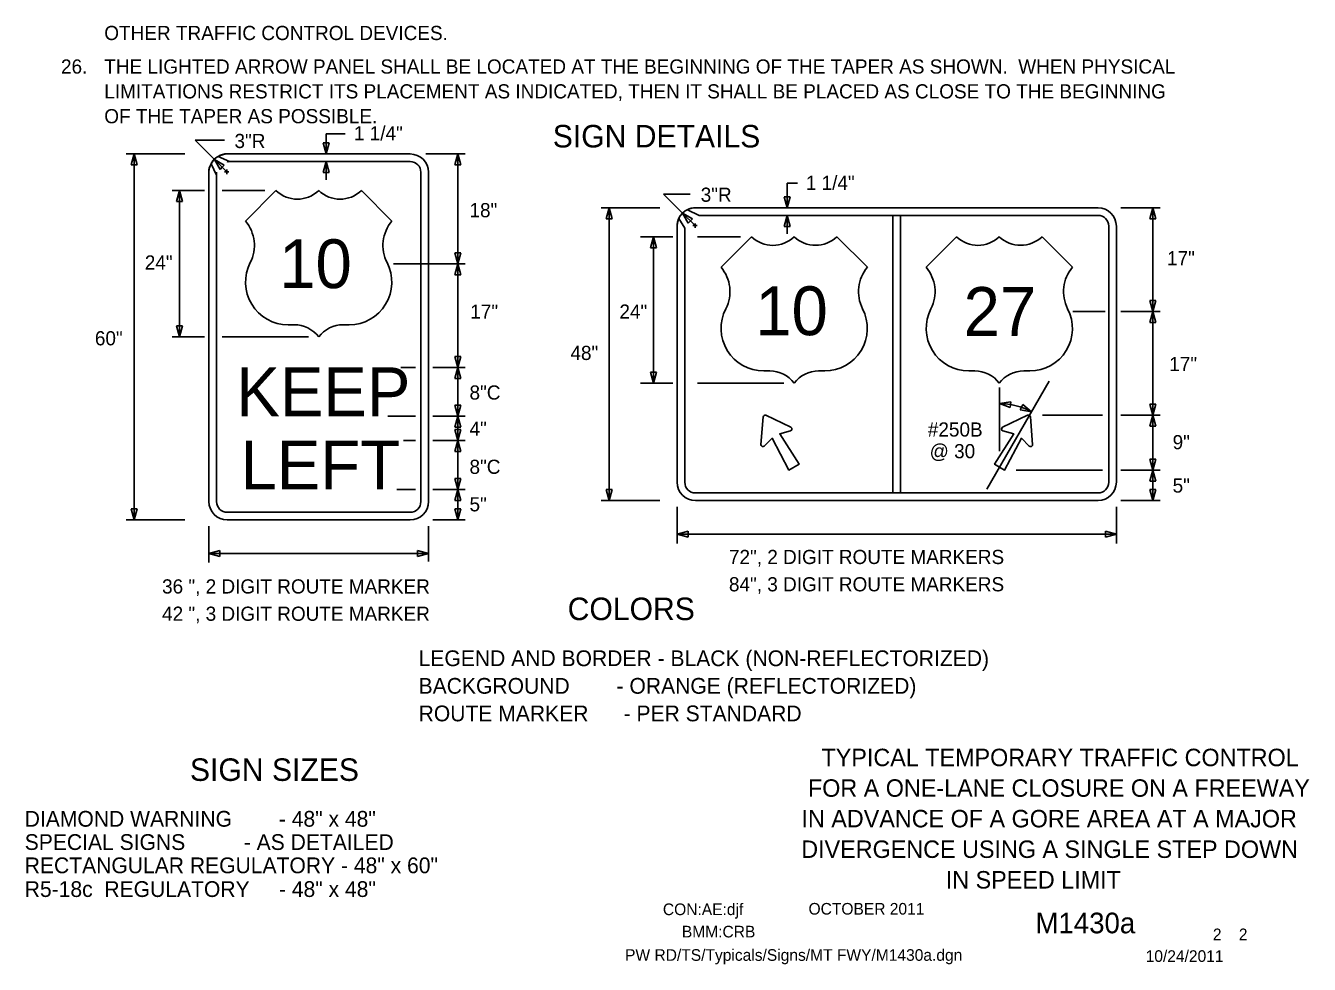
# Model space of a CAD drawing. Extents: x 16729 to 18500, y 5737 to 6974.
# Drawn here: x 17780 to 18464, y 5932 to 6432 of the extents above; entities that cross this region are included whole.
import ezdxf

# ---------------------------------------------------------------- set-up
doc = ezdxf.new("R2010")
doc.units = 0
for name, color, linetype in [('BORDER', 7, 'Continuous'), ('BORDER_SIGNAL_WO', 7, 'Continuous'), ('TRAFFIC_SIGNS_PR', 7, 'Continuous'), ('TYPICAL_EX', 7, 'Continuous'), ('TYPICAL_TEXT_DIMEN_PR', 7, 'Continuous')]:
    doc.layers.add(name, color=color, linetype=linetype)

msp = doc.modelspace()

# ---------------------------------------------------------------- linework, layer by layer
at = {"layer": 'TRAFFIC_SIGNS_PR'}
for p, q in [((17888.74, 6359.64), (17882.64, 6362.38)), ((17887.54, 6363.7), (17985.04, 6363.7)), ((17879.95, 6360.08), (17878.95, 6358.57)), ((17878.98, 6358.5), (17881.85, 6352.46)), ((17985.04, 6359.64), (17887.54, 6359.64)), ((17877.79, 6178.45), (17877.79, 6353.95)), ((17881.85, 6353.95), (17881.85, 6178.45)), ((17990.72, 6178.45), (17990.72, 6353.95)), ((17994.79, 6353.95), (17994.79, 6178.45)), ((18139.01, 6330.95), (18132.78, 6333.97)), ((18137.06, 6335), (18351.56, 6335)), ((18137.06, 6335), (18351.56, 6335)), ((18128.23, 6329.26), (18131.37, 6324.21)), ((18138.99, 6330.94), (18242.28, 6330.94)), ((18351.56, 6330.94), (18139, 6330.94)), ((18242.28, 6330.94), (18242.28, 6183.06)), ((18246.34, 6330.94), (18246.34, 6183.06)), ((18246.34, 6330.94), (18351.56, 6330.94)), ((18127.31, 6325.25), (18127.31, 6188.75)), ((18127.31, 6188.75), (18127.31, 6325.25)), ((18131.37, 6324.2), (18131.37, 6188.75)), ((18131.37, 6324.2), (18131.37, 6188.75)), ((18357.24, 6325.25), (18357.24, 6279.5)), ((18357.25, 6188.75), (18357.25, 6325.25)), ((18361.31, 6325.25), (18361.31, 6188.75)), ((18361.31, 6325.25), (18361.31, 6188.75)), ((18357.24, 6279.5), (18357.24, 6188.75)), ((18174.57, 6224.44), (18187.89, 6218.08)), ((18314.04, 6224.44), (18300.73, 6218.08)), ((18171.91, 6208.86), (18173.06, 6223.57)), ((18316.71, 6208.86), (18315.56, 6223.57)), ((18137.06, 6183.06), (18351.56, 6183.06)), ((18137.06, 6179), (18351.56, 6179)), ((18351.56, 6179), (18137.06, 6179)), ((17887.54, 6172.76), (17985.04, 6172.76)), ((17985.04, 6168.7), (17887.54, 6168.7))]:
    msp.add_line(p, q, dxfattribs=at)
for points in [[(18139, 6330.94), (18138.98, 6330.94)], [(18131.37, 6324.21), (18131.37, 6324.2)], [(18187.73, 6216.11), (18182, 6214.54), (18192.22, 6198.37), (18186.82, 6195.25), (18177.93, 6212.19), (18173.7, 6208.02)], [(18300.89, 6216.11), (18306.61, 6214.54), (18296.4, 6198.37), (18301.79, 6195.25), (18310.69, 6212.19), (18314.91, 6208.02)]]:
    msp.add_lwpolyline(points, dxfattribs=at)
msp.add_lwpolyline([(18242.28, 6330.94), (18246.34, 6330.94), (18246.34, 6183.06), (18242.28, 6183.06)], close=True, dxfattribs=at)
for centre, radius, start, end in [((17887.54, 6353.95), 9.75, 90, 180), ((17886.95, 6356.12), 7.6, 85.58319, 124.53531), ((17985.04, 6353.95), 9.75, 0, 90), ((17884.82, 6354.54), 7.06, 145.86811, 184.82317), ((17888.14, 6364.06), 4.47, 262.2432, 277.7568), ((17985.04, 6353.95), 5.69, 0, 90), ((17876.39, 6353.2), 5.51, 352.24294, 7.75653), ((18137.06, 6325.25), 9.75, 90, 180), ((18137.06, 6325.25), 9.75, 90, 180), ((18136.38, 6328.43), 6.6, 84.11162, 123.06374), ((18351.56, 6325.25), 9.75, 0, 90), ((18351.56, 6325.25), 9.75, 0, 90), ((18133.44, 6325.95), 6.17, 147.60925, 186.56283), ((18138, 6338.12), 7.24, 277.81035, 278.05403), ((18351.56, 6325.25), 5.69, 0, 89.99421), ((18351.56, 6325.25), 5.69, 0, 90), ((18174.12, 6223.49), 1.06, 64.48226, 175.51774), ((18314.5, 6223.49), 1.06, 4.48226, 115.51774), ((18187.43, 6217.13), 1.06, 285.9885, 64.48226), ((18301.18, 6217.13), 1.06, 115.51774, 254.0115), ((18172.97, 6208.78), 1.06, 175.51775, 314.01151), ((18315.65, 6208.78), 1.06, 225.98849, 4.48225), ((18137.06, 6188.75), 9.75, 180, 270), ((18137.06, 6188.75), 9.75, 180, 270), ((18137.06, 6188.75), 5.69, 180, 270), ((18137.06, 6188.75), 5.69, 180, 270), ((18351.56, 6188.75), 9.75, 270, 0), ((18351.56, 6188.75), 5.69, 270, 0), ((18351.56, 6188.75), 9.75, 270, 0), ((18351.56, 6188.75), 5.69, 270, 0), ((17887.54, 6178.45), 9.75, 180, 270), ((17887.54, 6178.45), 5.69, 180, 270), ((17985.04, 6178.45), 5.69, 270, 0), ((17985.04, 6178.45), 9.75, 270, 0)]:
    msp.add_arc(centre, radius, start, end, dxfattribs=at)
at = {"layer": 'TYPICAL_EX'}
for p, q in [((17897.29, 6327.95), (17913.54, 6344.2)), ((17975.29, 6327.95), (17959.04, 6344.2)), ((18150.67, 6303.34), (18166.92, 6319.59)), ((18228.67, 6303.34), (18212.42, 6319.59)), ((18259.95, 6303.34), (18276.2, 6319.59)), ((18337.95, 6303.34), (18321.7, 6319.59)), ((17920.01, 6272.66), (17923.26, 6272.66)), ((17952.56, 6272.66), (17949.31, 6272.66)), ((18173.4, 6248.05), (18176.65, 6248.05)), ((18205.94, 6248.05), (18202.69, 6248.05)), ((18282.67, 6248.05), (18285.92, 6248.05)), ((18315.22, 6248.05), (18311.97, 6248.05))]:
    msp.add_line(p, q, dxfattribs=at)
for centre, radius, start, end in [((17924.91, 6356.03), 16.42, 226.14041, 313.85958), ((17947.66, 6356.04), 16.42, 226.14042, 313.85959), ((17881.88, 6314.94), 20.16, 333.09768, 40.19361), ((17990.69, 6314.94), 20.16, 139.80639, 206.90233), ((18178.3, 6331.42), 16.42, 226.14041, 313.85958), ((18201.04, 6331.43), 16.42, 226.14042, 313.85959), ((18287.57, 6331.42), 16.42, 226.14041, 313.85958), ((18310.32, 6331.43), 16.42, 226.14042, 313.85959), ((17920.05, 6295.38), 22.73, 152.6698, 269.90132), ((17952.52, 6295.38), 22.73, 270.09868, 27.3302), ((18135.27, 6290.33), 20.16, 333.09768, 40.19361), ((18244.07, 6290.33), 20.16, 139.80639, 206.90233), ((18244.55, 6290.33), 20.16, 333.09768, 40.19361), ((18353.35, 6290.33), 20.16, 139.80639, 206.90233), ((18173.44, 6270.77), 22.73, 152.6698, 269.90132), ((18205.9, 6270.77), 22.73, 270.09868, 27.3302), ((18282.71, 6270.77), 22.73, 152.6698, 269.90132), ((18315.18, 6270.77), 22.73, 270.09868, 27.3302), ((17923.3, 6256.38), 16.28, 37.1038, 90.13853), ((17949.27, 6256.38), 16.28, 89.86147, 142.8962), ((18176.69, 6231.77), 16.28, 37.1038, 90.13853), ((18202.65, 6231.77), 16.28, 89.86147, 142.8962), ((18285.97, 6231.77), 16.28, 37.1038, 90.13853), ((18311.93, 6231.77), 16.28, 89.86147, 142.8962)]:
    msp.add_arc(centre, radius, start, end, dxfattribs=at)
at = {"layer": 'TYPICAL_TEXT_DIMEN_PR'}
for p, q in [((17886.16, 6370.98), (17870.5, 6370.98)), ((17870.5, 6370.98), (17880.74, 6360.74)), ((17940.26, 6363.7), (17938.69, 6369.56)), ((17938.69, 6369.56), (17940.26, 6369.56)), ((17940.26, 6374.46), (17940.26, 6363.7)), ((17940.26, 6374.46), (17950.36, 6374.46)), ((17940.26, 6369.56), (17941.83, 6369.56)), ((17941.83, 6369.56), (17940.26, 6363.7)), ((17864.96, 6363.7), (17833.66, 6363.7)), ((17836.43, 6357.84), (17838, 6363.7)), ((17838, 6363.7), (17838, 6168.7)), ((17838, 6363.7), (17839.57, 6357.84)), ((17993.33, 6363.7), (18014.29, 6363.7)), ((18008.82, 6357.84), (18010.39, 6363.7)), ((18010.39, 6363.7), (18010.39, 6305.2)), ((18010.39, 6363.7), (18011.96, 6357.84)), ((17838, 6357.84), (17836.43, 6357.84)), ((17839.57, 6357.84), (17838, 6357.84)), ((17880.74, 6360.74), (17887.3, 6354.19)), ((17883.77, 6355.49), (17880.74, 6360.74)), ((17880.74, 6360.74), (17885.99, 6357.71)), ((17884.88, 6356.6), (17883.77, 6355.49)), ((17885.99, 6357.71), (17884.88, 6356.6)), ((17886.09, 6354.19), (17888.5, 6354.19)), ((17887.3, 6352.98), (17887.3, 6355.4)), ((17938.74, 6353.77), (17940.31, 6359.64)), ((17940.31, 6359.64), (17940.31, 6349.89)), ((17940.31, 6359.64), (17941.88, 6353.77)), ((18010.39, 6357.84), (18008.82, 6357.84)), ((18011.96, 6357.84), (18010.39, 6357.84)), ((17940.31, 6353.77), (17938.74, 6353.77)), ((17941.88, 6353.77), (17940.31, 6353.77)), ((18185.92, 6348.15), (18185.92, 6335)), ((18185.92, 6348.15), (18191.44, 6348.15)), ((17875.41, 6344.2), (17858.29, 6344.2)), ((17860.61, 6338.34), (17862.18, 6344.2)), ((17862.18, 6344.2), (17862.18, 6266.2)), ((17862.18, 6344.2), (17863.75, 6338.34)), ((17907.65, 6344.2), (17884.78, 6344.2)), ((18134.2, 6342.28), (18120.02, 6342.28)), ((18120.02, 6342.28), (18130.17, 6332.14)), ((18185.92, 6335), (18184.34, 6340.86)), ((18184.34, 6340.86), (18185.92, 6340.86)), ((18185.92, 6340.86), (18187.49, 6340.86)), ((18187.49, 6340.86), (18185.92, 6335)), ((17862.18, 6338.34), (17860.61, 6338.34)), ((17863.75, 6338.34), (17862.18, 6338.34)), ((18118.08, 6335), (18086.78, 6335)), ((18089.55, 6329.14), (18091.12, 6335)), ((18091.12, 6335), (18091.12, 6179)), ((18091.12, 6335), (18092.69, 6329.14)), ((18363.68, 6335), (18384.64, 6335)), ((18379.17, 6329.14), (18380.74, 6335)), ((18380.74, 6335), (18380.74, 6279.75)), ((18380.74, 6335), (18382.31, 6329.14)), ((18091.12, 6329.14), (18089.55, 6329.14)), ((18092.69, 6329.14), (18091.12, 6329.14)), ((18130.17, 6332.14), (18136.82, 6325.49)), ((18133.21, 6326.88), (18130.17, 6332.14)), ((18130.17, 6332.14), (18135.43, 6329.1)), ((18134.32, 6327.99), (18133.21, 6326.88)), ((18135.43, 6329.1), (18134.32, 6327.99)), ((18184.39, 6325.07), (18185.96, 6330.94)), ((18184.39, 6325.07), (18185.96, 6330.94)), ((18185.96, 6330.94), (18185.96, 6321.19)), ((18185.96, 6330.94), (18187.53, 6325.07)), ((18185.96, 6330.94), (18187.53, 6325.07)), ((18380.74, 6329.14), (18379.17, 6329.14)), ((18382.31, 6329.14), (18380.74, 6329.14)), ((18135.61, 6325.49), (18138.03, 6325.49)), ((18136.82, 6324.28), (18136.82, 6326.7)), ((18185.96, 6325.07), (18184.39, 6325.07)), ((18185.96, 6325.07), (18184.39, 6325.07)), ((18187.53, 6325.07), (18185.96, 6325.07)), ((18187.53, 6325.07), (18185.96, 6325.07)), ((18124.94, 6319.59), (18107.81, 6319.59)), ((18113.1, 6313.73), (18114.67, 6319.59)), ((18114.67, 6313.73), (18113.1, 6313.73)), ((18114.67, 6319.59), (18114.67, 6241.59)), ((18114.67, 6319.59), (18116.25, 6313.73)), ((18116.25, 6313.73), (18114.67, 6313.73)), ((18161.04, 6319.59), (18138.16, 6319.59)), ((18010.39, 6305.2), (18008.82, 6311.06)), ((18008.82, 6311.06), (18010.39, 6311.06)), ((18010.39, 6311.06), (18011.96, 6311.06)), ((18011.96, 6311.06), (18010.39, 6305.2)), ((17976.18, 6305.2), (18014.29, 6305.2)), ((18008.82, 6299.34), (18010.39, 6305.2)), ((18010.39, 6305.2), (18010.39, 6249.95)), ((18010.39, 6305.2), (18011.96, 6299.34)), ((18010.39, 6299.34), (18008.82, 6299.34)), ((18011.96, 6299.34), (18010.39, 6299.34)), ((18338.12, 6279.75), (18355.27, 6279.75)), ((18363.68, 6279.75), (18384.64, 6279.75)), ((18380.74, 6279.75), (18379.17, 6285.61)), ((18379.17, 6285.61), (18380.74, 6285.61)), ((18379.17, 6273.89), (18380.74, 6279.75)), ((18380.74, 6285.61), (18382.31, 6285.61)), ((18382.31, 6285.61), (18380.74, 6279.75)), ((18380.74, 6279.75), (18380.74, 6224.5)), ((18380.74, 6279.75), (18382.31, 6273.89)), ((18380.74, 6273.89), (18379.17, 6273.89)), ((18382.31, 6273.89), (18380.74, 6273.89)), ((17875.41, 6266.2), (17858.29, 6266.2)), ((17862.18, 6266.2), (17860.61, 6272.06)), ((17860.61, 6272.06), (17862.18, 6272.06)), ((17862.18, 6272.06), (17863.75, 6272.06)), ((17863.75, 6272.06), (17862.18, 6266.2)), ((17930.78, 6266.2), (17884.78, 6266.2)), ((18010.39, 6249.95), (18008.82, 6255.81)), ((18008.82, 6255.81), (18010.39, 6255.81)), ((18010.39, 6255.81), (18011.96, 6255.81)), ((18011.96, 6255.81), (18010.39, 6249.95)), ((17980.11, 6249.95), (17987.8, 6249.95)), ((17997.16, 6249.95), (18014.29, 6249.95)), ((18008.82, 6244.09), (18010.39, 6249.95)), ((18010.39, 6249.95), (18010.39, 6223.95)), ((18010.39, 6249.95), (18011.96, 6244.09)), ((18114.67, 6241.59), (18113.1, 6247.45)), ((18113.1, 6247.45), (18114.67, 6247.45)), ((18114.67, 6247.45), (18116.25, 6247.45)), ((18116.25, 6247.45), (18114.67, 6241.59)), ((18010.39, 6244.09), (18008.82, 6244.09)), ((18011.96, 6244.09), (18010.39, 6244.09)), ((18124.94, 6241.59), (18107.81, 6241.59)), ((18184.16, 6241.59), (18138.16, 6241.59)), ((18292.34, 6185.1), (18325.58, 6242.69)), ((18299.1, 6205.25), (18299.1, 6239.25)), ((18299.12, 6230.69), (18305.12, 6231.65)), ((18305.12, 6231.65), (18304.96, 6230.09)), ((18010.39, 6223.95), (18008.82, 6229.81)), ((18008.82, 6229.81), (18010.39, 6229.81)), ((18010.39, 6229.81), (18011.96, 6229.81)), ((18011.96, 6229.81), (18010.39, 6223.95)), ((18304.8, 6228.53), (18299.12, 6230.69)), ((18304.96, 6230.09), (18304.8, 6228.53)), ((18310.11, 6227.37), (18310.79, 6228.78)), ((18316.08, 6226.24), (18310.11, 6227.37)), ((18310.79, 6228.78), (18311.48, 6230.2)), ((18311.48, 6230.2), (18316.08, 6226.24)), ((18322.05, 6224.5), (18353.92, 6224.5)), ((18363.68, 6224.5), (18384.64, 6224.5)), ((18380.74, 6224.5), (18379.17, 6230.36)), ((18379.17, 6230.36), (18380.74, 6230.36)), ((18379.17, 6218.64), (18380.74, 6224.5)), ((18380.74, 6230.36), (18382.31, 6230.36)), ((18382.31, 6230.36), (18380.74, 6224.5)), ((18380.74, 6224.5), (18380.74, 6195.25)), ((18380.74, 6224.5), (18382.31, 6218.64)), ((17973.1, 6223.95), (17987.8, 6223.95)), ((17997.16, 6223.95), (18014.29, 6223.95)), ((18008.82, 6218.09), (18010.39, 6223.95)), ((18010.39, 6218.09), (18008.82, 6218.09)), ((18010.39, 6223.95), (18010.39, 6210.95)), ((18010.39, 6223.95), (18011.96, 6218.09)), ((18011.96, 6218.09), (18010.39, 6218.09)), ((18380.74, 6218.64), (18379.17, 6218.64)), ((18382.31, 6218.64), (18380.74, 6218.64)), ((17981.45, 6210.95), (17987.8, 6210.95)), ((17997.16, 6210.95), (18014.29, 6210.95)), ((18010.39, 6210.95), (18008.82, 6216.81)), ((18008.82, 6216.81), (18010.39, 6216.81)), ((18008.82, 6205.09), (18010.39, 6210.95)), ((18010.39, 6216.81), (18011.96, 6216.81)), ((18011.96, 6216.81), (18010.39, 6210.95)), ((18010.39, 6210.95), (18010.39, 6184.95)), ((18010.39, 6210.95), (18011.96, 6205.09)), ((18010.39, 6205.09), (18008.82, 6205.09)), ((18011.96, 6205.09), (18010.39, 6205.09)), ((18380.74, 6195.25), (18379.17, 6201.11)), ((18379.17, 6201.11), (18380.74, 6201.11)), ((18380.74, 6201.11), (18382.31, 6201.11)), ((18382.31, 6201.11), (18380.74, 6195.25)), ((18010.39, 6184.95), (18008.82, 6190.81)), ((18008.82, 6190.81), (18010.39, 6190.81)), ((18010.39, 6190.81), (18011.96, 6190.81)), ((18011.96, 6190.81), (18010.39, 6184.95)), ((18307.91, 6195.25), (18353.92, 6195.25)), ((18363.68, 6195.25), (18384.64, 6195.25)), ((18379.17, 6189.39), (18380.74, 6195.25)), ((18380.74, 6195.25), (18380.74, 6179)), ((18380.74, 6195.25), (18382.31, 6189.39)), ((17977.95, 6184.95), (17987.8, 6184.95)), ((17997.16, 6184.95), (18014.29, 6184.95)), ((18008.82, 6179.09), (18010.39, 6184.95)), ((18010.39, 6184.95), (18010.39, 6168.7)), ((18010.39, 6184.95), (18011.96, 6179.09)), ((18091.12, 6179), (18089.55, 6184.86)), ((18089.55, 6184.86), (18091.12, 6184.86)), ((18091.12, 6184.86), (18092.69, 6184.86)), ((18092.69, 6184.86), (18091.12, 6179)), ((18380.74, 6189.39), (18379.17, 6189.39)), ((18380.74, 6179), (18379.17, 6184.86)), ((18379.17, 6184.86), (18380.74, 6184.86)), ((18382.31, 6189.39), (18380.74, 6189.39)), ((18380.74, 6184.86), (18382.31, 6184.86)), ((18382.31, 6184.86), (18380.74, 6179)), ((18010.39, 6179.09), (18008.82, 6179.09)), ((18011.96, 6179.09), (18010.39, 6179.09)), ((18118.08, 6179), (18086.78, 6179)), ((18363.68, 6179), (18380.81, 6179)), ((18363.68, 6179), (18384.64, 6179)), ((18363.68, 6179), (18380.81, 6179)), ((17838, 6168.7), (17836.43, 6174.56)), ((17836.43, 6174.56), (17838, 6174.56)), ((17838, 6174.56), (17839.57, 6174.56)), ((17839.57, 6174.56), (17838, 6168.7)), ((18010.39, 6168.7), (18008.82, 6174.56)), ((18008.82, 6174.56), (18010.39, 6174.56)), ((18010.39, 6174.56), (18011.96, 6174.56)), ((18011.96, 6174.56), (18010.39, 6168.7)), ((18127.31, 6175.65), (18127.31, 6156.09)), ((18361.31, 6175.65), (18361.31, 6156.09)), ((17864.96, 6168.7), (17833.66, 6168.7)), ((17877.79, 6165.35), (17877.79, 6146)), ((17994.79, 6165.35), (17994.79, 6146.46)), ((17997.16, 6168.7), (18014.29, 6168.7)), ((18127.31, 6161.03), (18133.17, 6162.6)), ((18127.31, 6161.03), (18361.31, 6161.03)), ((18133.17, 6159.46), (18127.31, 6161.03)), ((18133.17, 6162.6), (18133.17, 6161.03)), ((18133.17, 6161.03), (18133.17, 6159.46)), ((18355.45, 6161.03), (18355.45, 6162.6)), ((18355.45, 6162.6), (18361.31, 6161.03)), ((18361.31, 6161.03), (18355.45, 6159.46)), ((18355.45, 6159.46), (18355.45, 6161.03)), ((17877.79, 6150.73), (17883.65, 6152.3)), ((17877.79, 6150.73), (17994.79, 6150.73)), ((17883.65, 6149.15), (17877.79, 6150.73)), ((17883.65, 6152.3), (17883.65, 6150.73)), ((17883.65, 6150.73), (17883.65, 6149.15)), ((17988.92, 6150.73), (17988.92, 6152.3)), ((17988.92, 6152.3), (17994.79, 6150.73)), ((17994.79, 6150.73), (17988.92, 6149.15)), ((17988.92, 6149.15), (17988.92, 6150.73))]:
    msp.add_line(p, q, dxfattribs=at)
msp.add_arc((18299.29, 6196.25), 34.39, 60.74521, 90.32117, dxfattribs=at)

# ---------------------------------------------------------------- texts
at = {"layer": 'BORDER'}
for s, p in [('TYPICAL TEMPORARY TRAFFIC CONTROL', (18204.21, 6037.44)), ('FOR A ONE-LANE CLOSURE ON A FREEWAY', (18196.99, 6021.14)), ('IN ADVANCE OF A GORE AREA AT A MAJOR', (18193.54, 6004.84)), ('DIVERGENCE USING A SINGLE STEP DOWN ', (18193.42, 5988.54)), ('IN SPEED LIMIT', (18270.42, 5972.24))]:
    msp.add_text(s, height=9.3, dxfattribs=at).set_placement(p)
at = {"layer": 'BORDER_SIGNAL_WO'}
for s, height, p in [('CON:AE:djf  ', 6.2, (18119.69, 5958.06)), ('    OCTOBER 2011    ', 6.2, (18188.08, 5958.34)), ('    M1430a   ', 11, (18301.86, 5948.38)), ('BMM:CRB   ', 6.2, (18129.81, 5946.17)), (' 2    2 ', 6.2, (18410.45, 5944.7)), ('PW RD/TS/Typicals/Signs/MT FWY/M1430a.dgn      ', 6.2, (18099.55, 5933.71)), ('10/24/2011    ', 6.2, (18376.93, 5933.13))]:
    msp.add_text(s, height=height, dxfattribs=at).set_placement(p)
at = {"layer": 'TRAFFIC_SIGNS_PR'}
for s, p in [('10', (17915.26, 6292.2)), ('10', (18168.91, 6267.13)), ('27', (18279.91, 6266.77)), ('KEEP', (17892.39, 6223.95)), ('LEFT', (17894.62, 6184.95))]:
    msp.add_text(s, height=26, dxfattribs=at).set_placement(p)
at = {"layer": 'TYPICAL_TEXT_DIMEN_PR'}
for s, height, p in [('OTHER TRAFFIC CONTROL DEVICES.', 7.56, (17822.03, 6424.4)), ('26.', 7.56, (17798.98, 6406.52)), ('THE LIGHTED ARROW PANEL SHALL BE LOCATED AT THE BEGINNING OF THE TAPER AS SHOWN.  WHEN PHYSICAL', 7.56, (17822.03, 6406.52)), ('LIMITATIONS RESTRICT ITS PLACEMENT AS INDICATED, THEN IT SHALL BE PLACED AS CLOSE TO THE BEGINNING', 7.56, (17822.03, 6393.29)), ('OF THE TAPER AS POSSIBLE.', 7.56, (17822.03, 6380.06)), ('1 1/4"', 7.55, (17955.06, 6370.95)), ('SIGN DETAILS', 12, (18061.01, 6367.17)), ('3"R', 7.55, (17891.42, 6366.86)), ('1 1/4"', 7.55, (18195.84, 6344.57)), ('3"R', 7.55, (18139.84, 6338.2)), ('18"', 7.55, (18016.63, 6329.97)), ('24"', 7.55, (17843.63, 6302.08)), ('17"', 7.55, (18388.32, 6304.36)), ('17"', 7.55, (18017.08, 6275.92)), ('24"', 7.55, (18096.53, 6275.92)), ('60"', 7.55, (17817.03, 6261.71)), ('48"', 7.55, (18070.42, 6253.9)), ('17"', 7.55, (18389.52, 6248)), ('8"C', 7.55, (18016.66, 6232.8)), ('4" ', 7.55, (18016.66, 6213.54)), ('#250B', 7.55, (18260.87, 6213.09)), ('9"', 7.55, (18391.3, 6206.34)), ('@ 30', 7.55, (18261.81, 6201.54)), ('8"C', 7.55, (18016.66, 6193.22)), ('5"', 7.55, (18391.3, 6183.24)), ('5" ', 7.55, (18016.66, 6173.24)), ('72", 2 DIGIT ROUTE MARKERS', 7.55, (18154.89, 6145.16)), ('36 ", 2 DIGIT ROUTE MARKER', 7.55, (17852.83, 6129.46)), ('84", 3 DIGIT ROUTE MARKERS', 7.55, (18154.89, 6130.61)), ('42 ", 3 DIGIT ROUTE MARKER', 7.55, (17852.83, 6114.91)), ('COLORS', 12, (18068.95, 6115.28)), ('LEGEND AND BORDER - BLACK (NON-REFLECTORIZED)', 8.4, (17989.53, 6090.75)), ('BACKGROUND        - ORANGE (REFLECTORIZED)', 8.4, (17989.53, 6076.05)), ('ROUTE MARKER      - PER STANDARD', 8.4, (17989.53, 6061.35)), ('SIGN SIZES', 12, (17867.69, 6029.59)), ('DIAMOND WARNING        - 48" x 48"', 8.4, (17779.65, 6005.19)), ('SPECIAL SIGNS          - AS DETAILED', 8.4, (17779.65, 5992.79)), ('RECTANGULAR REGULATORY - 48" x 60"', 8.4, (17779.65, 5980.39)), ('R5-18c  REGULATORY     - 48" x 48"', 8.4, (17779.65, 5967.74))]:
    msp.add_text(s, height=height, dxfattribs=at).set_placement(p)

doc.saveas('drawing.dxf')
